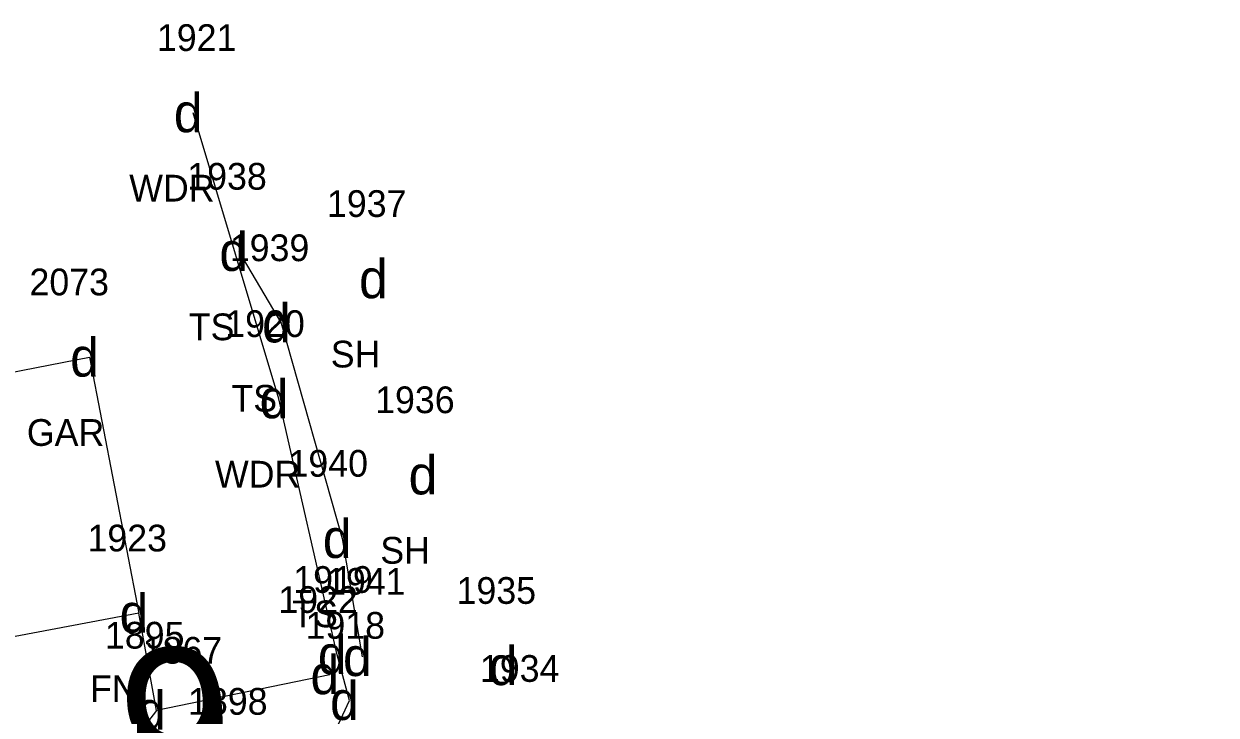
# Model space of a CAD drawing. Extents: x 461160 to 461373, y 202903 to 203086.
# Drawn here: x 461338.05 to 461371.96, y 203026.97 to 203046.62 of the extents above; entities that cross this region are included whole.
import ezdxf

# ---------------------------------------------------------------- set-up
doc = ezdxf.new("R2010")
doc.units = 0
for name, color, linetype in [('Level 12', 7, 'Continuous'), ('Level 13', 7, 'Continuous'), ('Level 14', 7, 'Continuous'), ('Level 15', 7, 'Continuous'), ('Level 46', 7, 'Continuous'), ('Level 47', 7, 'Continuous'), ('Level 48', 7, 'Continuous'), ('Level 49', 7, 'Continuous')]:
    doc.layers.add(name, color=color, linetype=linetype)

msp = doc.modelspace()

# ---------------------------------------------------------------- linework, layer by layer
at = {"layer": 'Level 12'}
msp.add_lwpolyline([(461346.75, 203028.112), (461341.818, 203027.098), (461341.321, 203029.861)], dxfattribs=at)
at = {"layer": 'Level 13'}
for points in [[(461334.073, 203028.503), (461332.617, 203035.719), (461339.916, 203037.142), (461341.321, 203029.861)], [(461341.321, 203029.861), (461334.073, 203028.503)]]:
    msp.add_lwpolyline(points, dxfattribs=at)
at = {"layer": 'Level 14'}
msp.add_lwpolyline([(461371.96, 203001.923), (461367.033, 203004.874), (461360.264, 203009.277), (461355.544, 203013.756), (461349.355, 203019.397), (461345.522, 203023.52), (461347.307, 203027.378), (461346.96, 203028.682), (461345.303, 203035.957), (461342.864, 203044.09)], dxfattribs=at)
at = {"layer": 'Level 48'}
for points in [[(461344.159, 203040.146), (461345.372, 203038.114), (461347.101, 203031.985), (461347.675, 203028.628)], [(461344.159, 203040.146), (461345.372, 203038.114), (461347.101, 203031.985), (461347.675, 203028.628)], [(461341.818, 203027.098), (461339.64, 203024.274), (461340.078, 203023.683), (461344.181, 203025.217), (461344.597, 203023.722), (461341.064, 203022.254)], [(461341.818, 203027.098), (461339.64, 203024.274), (461340.078, 203023.683), (461344.181, 203025.217), (461344.597, 203023.722), (461341.064, 203022.254)]]:
    msp.add_lwpolyline(points, dxfattribs=at)

# ---------------------------------------------------------------- texts
at = {"layer": 'Level 15'}
msp.add_text('9', height=4.4, dxfattribs=at).set_placement((461340.708, 203024.469))
at = {"layer": 'Level 46'}
for s, p in [(' WDR  ', (461340.764, 203041.57)), (' TS  ', (461342.457, 203037.626)), (' SH  ', (461346.496, 203036.851)), (' TS  ', (461343.67, 203035.594)), (' GAR  ', (461337.852, 203034.622)), (' WDR  ', (461343.203, 203033.437)), (' SH  ', (461347.905, 203031.272)), (' TS  ', (461345.399, 203029.465)), (' FN  ', (461339.646, 203027.341))]:
    msp.add_text(s, height=0.76, dxfattribs=at).set_placement(p)
at = {"layer": 'Level 47'}
for p in [(461342.314, 203043.54), (461343.609, 203039.596), (461347.582, 203038.821), (461344.822, 203037.564), (461339.366, 203036.592), (461344.753, 203035.407), (461348.991, 203033.242), (461346.551, 203031.435), (461340.771, 203029.311), (461346.41, 203028.132), (461347.125, 203028.078), (461351.268, 203027.82), (461346.2, 203027.562), (461346.757, 203026.828), (461341.268, 203026.548)]:
    msp.add_text('d', height=1.1, dxfattribs=at).set_placement(p)
at = {"layer": 'Level 49'}
for s, p in [(' 1921 ', (461341.551, 203045.85)), (' 1938 ', (461342.415, 203041.906)), (' 1937 ', (461346.388, 203041.131)), (' 1939 ', (461343.625, 203039.874)), (' 2073 ', (461337.927, 203038.902)), (' 1920 ', (461343.496, 203037.717)), (' 1936 ', (461347.758, 203035.552)), (' 1940 ', (461345.294, 203033.745)), (' 1923 ', (461339.577, 203031.621)), (' 1919 ', (461345.429, 203030.442)), (' 1941 ', (461346.362, 203030.388)), (' 1922 ', (461345.006, 203029.872)), (' 1935 ', (461350.074, 203030.13)), (' 1895 ', (461340.074, 203028.858)), (' 1918 ', (461345.779, 203029.138)), (' 1867 ', (461341.146, 203028.429)), (' 1934 ', (461350.738, 203027.912)), (' 1898 ', (461342.437, 203026.977))]:
    msp.add_text(s, height=0.76, dxfattribs=at).set_placement(p)

doc.saveas('drawing.dxf')
